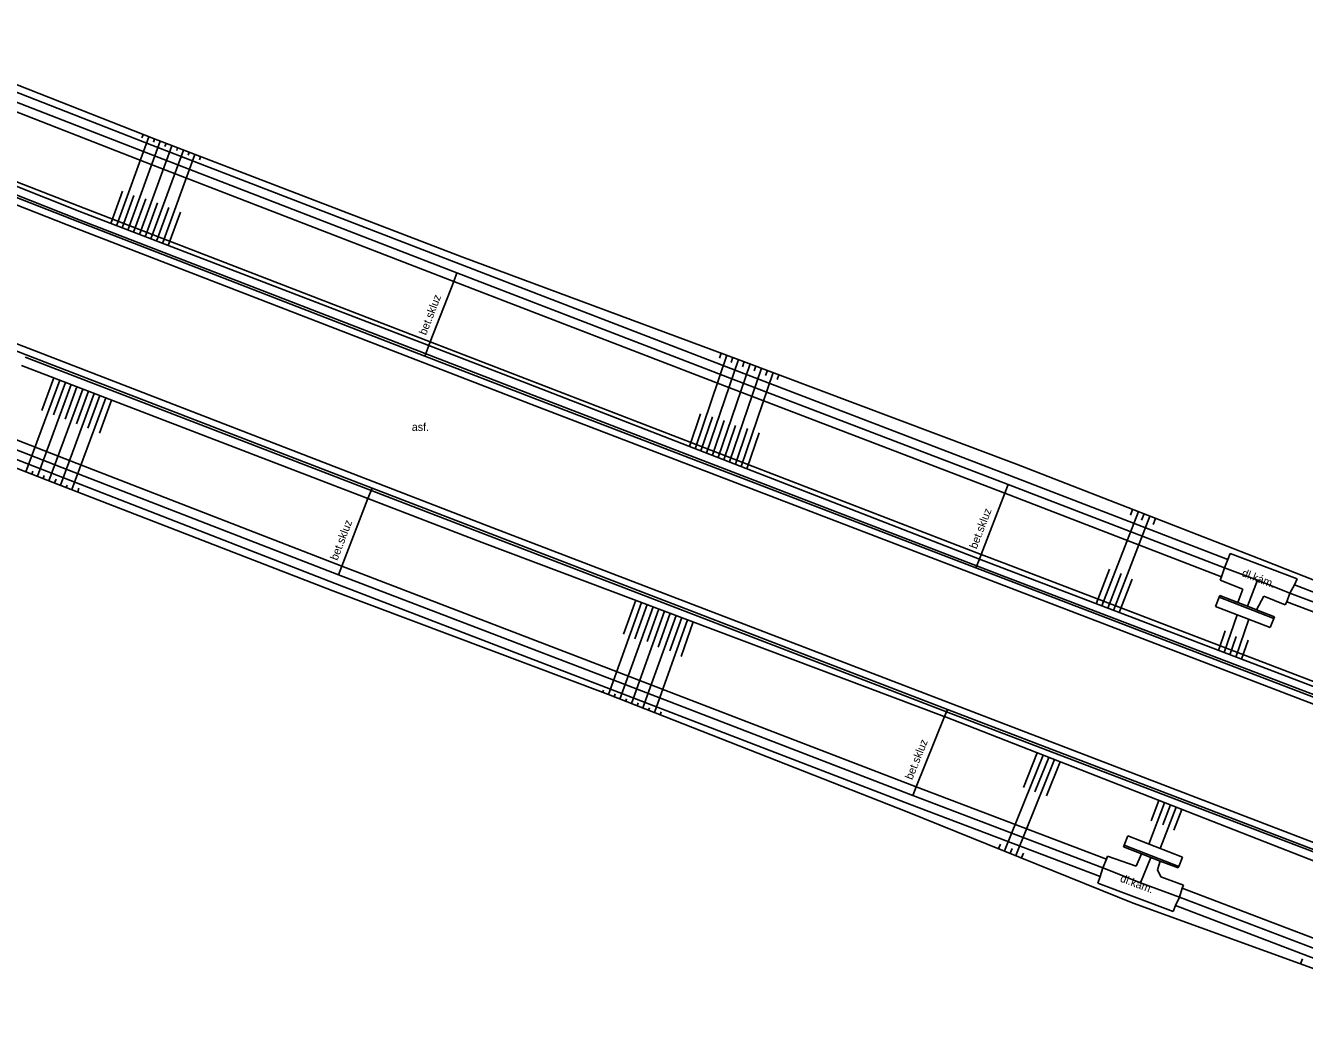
# Model space of a CAD drawing. Extents: x -541281 to -539153, y -1183881 to -1182141.
# Drawn here: x -539526 to -539422.2, y -1182433.5 to -1182351.9 of the extents above; entities that cross this region are included whole.
import ezdxf

# ---------------------------------------------------------------- set-up
doc = ezdxf.new("R2010")
doc.units = 0
for name, color, linetype in [('Vrstva 10', 7, 'Continuous'), ('Vrstva 11', 7, 'Continuous'), ('Vrstva 14', 7, 'Continuous'), ('Vrstva 15', 7, 'Continuous'), ('Vrstva 40', 7, 'Continuous'), ('Vrstva 7', 7, 'Continuous'), ('Vrstva 9', 7, 'Continuous')]:
    doc.layers.add(name, color=color, linetype=linetype)

msp = doc.modelspace()

# ---------------------------------------------------------------- linework, layer by layer
at = {"layer": 'Vrstva 10'}
for p, q in [((-539559.23, -1182353.77), (-539521.89, -1182368.36)), ((-539525.83, -1182378.1), (-539563.06, -1182363.54)), ((-539521.89, -1182368.36), (-539484.65, -1182382.76)), ((-539488.45, -1182392.54), (-539525.83, -1182378.1)), ((-539484.65, -1182382.76), (-539447.3, -1182397.1)), ((-539451.1, -1182406.87), (-539488.45, -1182392.54)), ((-539447.3, -1182397.1), (-539409.95, -1182411.4)), ((-539413.74, -1182421.2), (-539451.1, -1182406.87))]:
    msp.add_line(p, q, dxfattribs=at)
at = {"layer": 'Vrstva 11'}
for p, q in [((-539515.77, -1182361.59), (-539539.15, -1182352.46)), ((-539516.32, -1182362.99), (-539539.7, -1182353.86)), ((-539490.73, -1182371.27), (-539515.77, -1182361.59)), ((-539491.27, -1182372.67), (-539516.32, -1182362.99)), ((-539468.4, -1182379.87), (-539490.73, -1182371.27)), ((-539468.93, -1182381.27), (-539491.27, -1182372.67)), ((-539546.97, -1182377.69), (-539522.34, -1182387.26)), ((-539547.52, -1182379.08), (-539522.88, -1182388.65)), ((-539445.97, -1182388.47), (-539468.4, -1182379.87)), ((-539446.51, -1182389.87), (-539468.93, -1182381.27)), ((-539522.34, -1182387.26), (-539500.35, -1182395.8)), ((-539522.88, -1182388.65), (-539500.89, -1182397.2)), ((-539428.41, -1182395.24), (-539445.97, -1182388.47)), ((-539428.93, -1182396.65), (-539446.51, -1182389.87)), ((-539451.17, -1182407.43), (-539488.6, -1182393.04)), ((-539422.77, -1182396.82), (-539428.22, -1182394.75)), ((-539500.35, -1182395.8), (-539477.99, -1182404.36)), ((-539500.89, -1182397.2), (-539478.53, -1182405.77)), ((-539409.68, -1182410.93), (-539447.04, -1182396.64)), ((-539429.04, -1182396.94), (-539427.18, -1182397.67)), ((-539397.51, -1182407.03), (-539423, -1182397.32)), ((-539429.1, -1182398.32), (-539424.67, -1182400.04)), ((-539427.18, -1182397.67), (-539427.6, -1182398.74)), ((-539426.07, -1182399.34), (-539425.48, -1182398.23)), ((-539425.48, -1182398.23), (-539423.75, -1182398.94)), ((-539429.4, -1182399.06), (-539424.96, -1182400.78)), ((-539398.04, -1182408.43), (-539423.63, -1182398.68)), ((-539477.99, -1182404.36), (-539453.72, -1182413.71)), ((-539478.53, -1182405.77), (-539454.26, -1182415.11)), ((-539414.01, -1182421.65), (-539451.17, -1182407.43)), ((-539453.72, -1182413.71), (-539438.26, -1182419.59)), ((-539454.26, -1182415.11), (-539438.78, -1182421)), ((-539436.53, -1182417.7), (-539432.1, -1182419.42)), ((-539436.82, -1182418.45), (-539432.39, -1182420.17)), ((-539435.42, -1182419.15), (-539435.86, -1182420.16)), ((-539435.86, -1182420.16), (-539438.18, -1182419.35)), ((-539434.12, -1182420.44), (-539433.89, -1182419.74)), ((-539433.85, -1182421.01), (-539434.12, -1182420.44)), ((-539432.01, -1182421.7), (-539433.85, -1182421.01)), ((-539438.97, -1182421.53), (-539432.84, -1182423.85)), ((-539432.11, -1182421.95), (-539407.04, -1182431.53)), ((-539432.65, -1182423.35), (-539407.58, -1182432.93))]:
    msp.add_line(p, q, dxfattribs=at)
for points in [[(-539521.66, -1182367.86), (-539542.05, -1182359.88), (-539559.03, -1182353.24)], [(-539525.99, -1182378.64), (-539544.52, -1182371.4), (-539563.19, -1182364.11)], [(-539484.48, -1182382.26), (-539493.61, -1182378.73), (-539521.66, -1182367.86)], [(-539488.6, -1182393.04), (-539497.9, -1182389.46), (-539525.99, -1182378.64)], [(-539447.04, -1182396.64), (-539448.86, -1182395.94), (-539484.48, -1182382.26)], [(-539428.22, -1182394.75), (-539428.41, -1182395.24), (-539428.68, -1182395.94), (-539428.93, -1182396.65), (-539429.04, -1182396.94)], [(-539423.75, -1182398.94), (-539423.63, -1182398.68), (-539423.36, -1182397.98), (-539423, -1182397.32), (-539422.77, -1182396.82)], [(-539429.05, -1182398.18), (-539429.1, -1182398.32), (-539429.4, -1182399.06)], [(-539429.05, -1182398.18), (-539427.6, -1182398.74), (-539426.82, -1182399.04), (-539426.07, -1182399.34), (-539424.62, -1182399.9)], [(-539424.62, -1182399.9), (-539424.67, -1182400.04), (-539424.96, -1182400.78)], [(-539436.88, -1182418.59), (-539436.82, -1182418.45), (-539436.53, -1182417.7)], [(-539436.88, -1182418.59), (-539435.42, -1182419.15), (-539434.65, -1182419.45), (-539433.89, -1182419.74), (-539432.44, -1182420.3)], [(-539438.18, -1182419.35), (-539438.26, -1182419.59), (-539438.55, -1182420.29), (-539438.78, -1182421), (-539438.97, -1182421.53)], [(-539432.44, -1182420.3), (-539432.39, -1182420.17), (-539432.1, -1182419.42)], [(-539432.84, -1182423.85), (-539432.65, -1182423.35), (-539432.34, -1182422.67), (-539432.11, -1182421.95), (-539432.01, -1182421.7)]]:
    msp.add_lwpolyline(points, dxfattribs=at)
at = {"layer": 'Vrstva 14'}
for p, q in [((-539538.98, -1182351.89), (-539515.65, -1182361.07)), ((-539516.05, -1182362.29), (-539539.42, -1182353.16)), ((-539515.65, -1182361.07), (-539490.6, -1182370.67)), ((-539491, -1182371.97), (-539516.05, -1182362.29)), ((-539490.6, -1182370.67), (-539468.17, -1182379)), ((-539491.27, -1182372.67), (-539491, -1182371.97)), ((-539468.67, -1182380.57), (-539491, -1182371.97)), ((-539493.17, -1182377.57), (-539491.27, -1182372.67)), ((-539493.29, -1182377.88), (-539493.17, -1182377.57)), ((-539547.24, -1182378.39), (-539522.61, -1182387.96)), ((-539493.61, -1182378.73), (-539493.29, -1182377.88)), ((-539523.16, -1182389.23), (-539547.78, -1182379.73)), ((-539468.17, -1182379), (-539445.56, -1182387.5)), ((-539446.24, -1182389.17), (-539468.67, -1182380.57)), ((-539522.61, -1182387.96), (-539500.62, -1182396.5)), ((-539445.56, -1182387.5), (-539425.39, -1182395.37)), ((-539501.09, -1182397.8), (-539523.16, -1182389.23)), ((-539497.9, -1182389.46), (-539498.23, -1182390.3)), ((-539428.68, -1182395.94), (-539446.24, -1182389.17)), ((-539488.96, -1182393.86), (-539451.44, -1182408)), ((-539448.86, -1182395.94), (-539448.57, -1182395.21)), ((-539448.57, -1182395.21), (-539448.43, -1182394.84)), ((-539446.73, -1182395.93), (-539409.38, -1182410.19)), ((-539426, -1182396.94), (-539428.68, -1182395.94)), ((-539425.39, -1182395.37), (-539397.22, -1182406.44)), ((-539500.62, -1182396.5), (-539478.26, -1182405.06)), ((-539426, -1182396.94), (-539426.82, -1182399.04)), ((-539423.36, -1182397.98), (-539426, -1182396.94)), ((-539478.71, -1182406.21), (-539501.09, -1182397.8)), ((-539397.77, -1182407.73), (-539423.36, -1182397.98)), ((-539478.26, -1182405.06), (-539453.99, -1182414.41)), ((-539454.44, -1182415.73), (-539478.71, -1182406.21)), ((-539451.17, -1182407.43), (-539451.41, -1182408.01)), ((-539453.99, -1182414.41), (-539438.55, -1182420.29)), ((-539436.09, -1182423.15), (-539454.44, -1182415.73)), ((-539435.49, -1182421.51), (-539434.65, -1182419.45)), ((-539438.55, -1182420.29), (-539435.49, -1182421.51)), ((-539435.49, -1182421.51), (-539432.34, -1182422.67)), ((-539407.69, -1182433.5), (-539436.09, -1182423.15)), ((-539432.34, -1182422.67), (-539407.31, -1182432.23))]:
    msp.add_line(p, q, dxfattribs=at)
for points in [[(-539551.08, -1182355.27), (-539541.71, -1182359), (-539521.5, -1182367.05)], [(-539521.5, -1182367.05), (-539493.29, -1182377.88), (-539484.16, -1182381.39)], [(-539526.35, -1182379.5), (-539498.23, -1182390.3), (-539488.96, -1182393.86)], [(-539484.16, -1182381.39), (-539448.57, -1182395.21), (-539446.73, -1182395.93)], [(-539448.43, -1182394.84), (-539446.51, -1182389.87), (-539446.24, -1182389.17)], [(-539498.23, -1182390.3), (-539500.35, -1182395.8), (-539500.62, -1182396.5)], [(-539451.41, -1182408.01), (-539453.72, -1182413.71), (-539453.99, -1182414.41)], [(-539451.44, -1182408), (-539451.41, -1182408.01), (-539414.32, -1182422.5)]]:
    msp.add_lwpolyline(points, dxfattribs=at)
at = {"layer": 'Vrstva 15'}
for p, q in [((-539518.66, -1182368.14), (-539516.02, -1182360.93)), ((-539516.58, -1182361.01), (-539516.49, -1182360.75)), ((-539517.72, -1182368.5), (-539515.09, -1182361.29)), ((-539516.79, -1182368.86), (-539514.15, -1182361.65)), ((-539515.86, -1182369.22), (-539513.22, -1182362.01)), ((-539515.64, -1182361.35), (-539515.56, -1182361.11)), ((-539514.71, -1182361.71), (-539514.62, -1182361.47)), ((-539513.76, -1182362.03), (-539513.69, -1182361.83)), ((-539514.92, -1182369.58), (-539512.29, -1182362.36)), ((-539512.84, -1182362.42), (-539512.75, -1182362.18)), ((-539511.91, -1182362.79), (-539511.82, -1182362.54)), ((-539519.12, -1182367.96), (-539518.16, -1182365.34)), ((-539518.19, -1182368.32), (-539517.23, -1182365.69)), ((-539517.26, -1182368.68), (-539516.27, -1182365.97)), ((-539516.32, -1182369.04), (-539515.32, -1182366.29)), ((-539515.39, -1182369.4), (-539514.39, -1182366.66)), ((-539514.46, -1182369.76), (-539513.46, -1182367.04)), ((-539471.66, -1182386.25), (-539469.08, -1182378.66)), ((-539469.69, -1182378.9), (-539469.55, -1182378.48)), ((-539470.73, -1182386.61), (-539468.14, -1182379.01)), ((-539469.79, -1182386.97), (-539467.2, -1182379.36)), ((-539468.86, -1182387.33), (-539466.27, -1182379.71)), ((-539468.75, -1182379.26), (-539468.61, -1182378.83)), ((-539467.81, -1182379.59), (-539467.67, -1182379.18)), ((-539466.87, -1182379.94), (-539466.74, -1182379.53)), ((-539523.26, -1182380.69), (-539526, -1182388.13)), ((-539523.73, -1182380.51), (-539524.7, -1182383.16)), ((-539467.93, -1182387.7), (-539465.33, -1182380.06)), ((-539465.94, -1182380.3), (-539465.8, -1182379.89)), ((-539465, -1182380.64), (-539464.86, -1182380.24)), ((-539522.32, -1182381.05), (-539525.07, -1182388.49)), ((-539521.39, -1182381.41), (-539524.13, -1182388.85)), ((-539522.79, -1182380.87), (-539523.76, -1182383.49)), ((-539520.46, -1182381.77), (-539523.2, -1182389.21)), ((-539521.86, -1182381.23), (-539522.82, -1182383.85)), ((-539520.93, -1182381.59), (-539521.9, -1182384.24)), ((-539519.52, -1182382.12), (-539522.27, -1182389.57)), ((-539519.99, -1182381.94), (-539520.97, -1182384.59)), ((-539519.06, -1182382.3), (-539520.04, -1182384.98)), ((-539472.12, -1182386.06), (-539471.23, -1182383.43)), ((-539471.19, -1182386.43), (-539470.25, -1182383.66)), ((-539470.26, -1182386.79), (-539469.3, -1182383.96)), ((-539469.33, -1182387.15), (-539468.38, -1182384.36)), ((-539468.39, -1182387.51), (-539467.41, -1182384.62)), ((-539467.46, -1182387.88), (-539466.47, -1182384.96)), ((-539525.45, -1182388.08), (-539525.53, -1182388.31)), ((-539524.51, -1182388.42), (-539524.6, -1182388.67)), ((-539523.56, -1182388.73), (-539523.67, -1182389.03)), ((-539522.66, -1182389.2), (-539522.73, -1182389.39)), ((-539521.7, -1182389.47), (-539521.8, -1182389.76)), ((-539436.31, -1182391.64), (-539436.14, -1182391.18)), ((-539438.63, -1182399.02), (-539435.67, -1182391.36)), ((-539437.7, -1182399.38), (-539434.74, -1182391.73)), ((-539435.41, -1182392.06), (-539435.2, -1182391.54)), ((-539434.46, -1182392.41), (-539434.27, -1182391.91)), ((-539439.1, -1182398.85), (-539438.01, -1182396.04)), ((-539438.16, -1182399.2), (-539437.08, -1182396.4)), ((-539437.23, -1182399.56), (-539436.18, -1182396.85)), ((-539476.02, -1182398.74), (-539478.7, -1182406.21)), ((-539475.08, -1182399.09), (-539477.77, -1182406.58)), ((-539476.49, -1182398.56), (-539477.47, -1182401.32)), ((-539474.15, -1182399.44), (-539476.83, -1182406.94)), ((-539475.55, -1182398.91), (-539476.55, -1182401.7)), ((-539474.61, -1182399.27), (-539475.56, -1182401.91)), ((-539473.21, -1182399.79), (-539475.9, -1182407.31)), ((-539472.28, -1182400.15), (-539474.97, -1182407.67)), ((-539473.68, -1182399.62), (-539474.67, -1182402.38)), ((-539472.74, -1182399.97), (-539473.71, -1182402.68)), ((-539471.81, -1182400.32), (-539472.81, -1182403.12)), ((-539427.65, -1182399.74), (-539428.7, -1182402.81)), ((-539426.71, -1182400.1), (-539427.77, -1182403.17)), ((-539428.63, -1182401.05), (-539429.17, -1182402.64)), ((-539427.73, -1182401.51), (-539428.24, -1182402.99)), ((-539426.77, -1182401.8), (-539427.3, -1182403.35)), ((-539479.1, -1182405.85), (-539479.17, -1182406.04)), ((-539478.15, -1182406.17), (-539478.23, -1182406.4)), ((-539477.23, -1182406.57), (-539477.3, -1182406.76)), ((-539476.28, -1182406.89), (-539476.37, -1182407.13)), ((-539475.37, -1182407.3), (-539475.44, -1182407.49)), ((-539474.42, -1182407.61), (-539474.51, -1182407.86)), ((-539443.41, -1182411.14), (-539446.55, -1182418.92)), ((-539442.48, -1182411.5), (-539445.63, -1182419.3)), ((-539443.88, -1182410.95), (-539445.01, -1182413.77)), ((-539442.95, -1182411.32), (-539444.08, -1182414.12)), ((-539442.02, -1182411.68), (-539443.13, -1182414.44)), ((-539434.82, -1182418.36), (-539433.54, -1182415)), ((-539434.64, -1182416.48), (-539434.01, -1182414.81)), ((-539433.89, -1182418.73), (-539432.61, -1182415.36)), ((-539433.69, -1182416.8), (-539433.07, -1182415.18)), ((-539432.78, -1182417.22), (-539432.14, -1182415.54)), ((-539446.87, -1182418.36), (-539447.02, -1182418.73)), ((-539445.93, -1182418.71), (-539446.09, -1182419.11)), ((-539445.01, -1182419.1), (-539445.16, -1182419.48)), ((-539422.35, -1182427.68), (-539422.5, -1182428.1))]:
    msp.add_line(p, q, dxfattribs=at)
at = {"layer": 'Vrstva 7'}
msp.add_line((-539399.93, -1182413.38), (-539446.57, -1182395.55), dxfattribs=at)
for points in [[(-539521.27, -1182366.73), (-539541.62, -1182358.79), (-539551.13, -1182355.08)], [(-539446.57, -1182395.55), (-539448.43, -1182394.84), (-539493.17, -1182377.57), (-539521.27, -1182366.73)]]:
    msp.add_lwpolyline(points, dxfattribs=at)
at = {"layer": 'Vrstva 9'}
for p, q in [((-539521.59, -1182367.68), (-539558.96, -1182353.05)), ((-539484.41, -1182382.08), (-539521.59, -1182367.68)), ((-539526.06, -1182378.82), (-539488.68, -1182393.23)), ((-539446.97, -1182396.46), (-539484.41, -1182382.08)), ((-539488.68, -1182393.23), (-539451.24, -1182407.62)), ((-539409.61, -1182410.74), (-539446.97, -1182396.46)), ((-539451.24, -1182407.62), (-539414.08, -1182421.83))]:
    msp.add_line(p, q, dxfattribs=at)

# ---------------------------------------------------------------- texts
at = {"layer": 'Vrstva 40'}
for s, rotation, p in [('bet.skluz', 68.8302, (-539493.51, -1182377.08)), ('bet.skluz', 68.8831, (-539448.81, -1182394.44)), ('bet.skluz', 68.9276, (-539500.72, -1182395.38)), ('dl.kám.', 339.2198, (-539427.33, -1182396.59)), ('bet.skluz', 68.0246, (-539454.04, -1182413.19)), ('dl.kám.', 339.3314, (-539437.21, -1182421.39))]:
    msp.add_text(s, height=0.65, rotation=rotation, dxfattribs=at).set_placement(p)
msp.add_text('asf.', height=0.65, dxfattribs=at).set_placement((-539494.67, -1182384.81))

doc.saveas('drawing.dxf')
